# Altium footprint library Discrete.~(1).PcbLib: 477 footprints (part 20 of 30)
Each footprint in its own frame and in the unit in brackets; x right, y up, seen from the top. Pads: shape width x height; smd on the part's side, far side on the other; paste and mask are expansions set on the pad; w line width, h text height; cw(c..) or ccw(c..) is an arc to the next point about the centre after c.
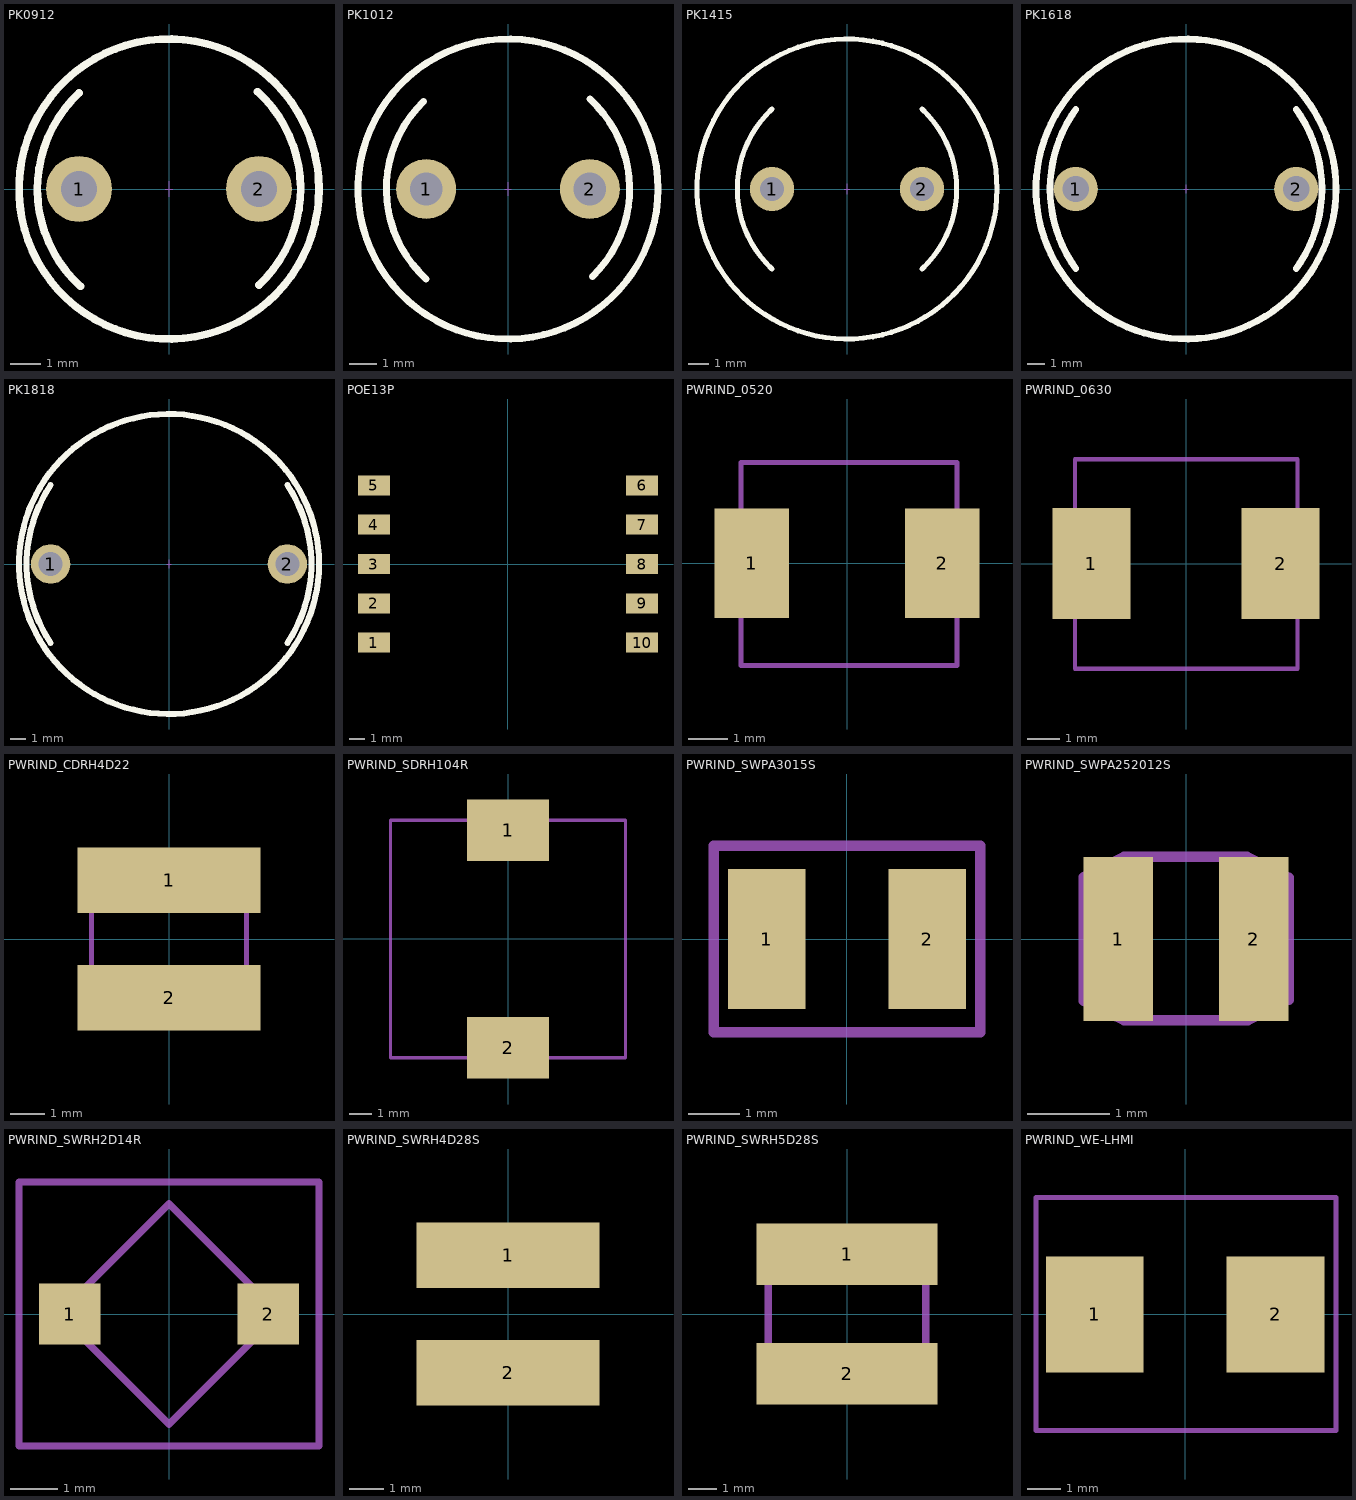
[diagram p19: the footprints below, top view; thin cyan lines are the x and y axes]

## PK0912 [mm] "6*10*14mm(脚距，直径，高）"
pads (2):
  round 2.2 hole 1.2: 1(-3,0) 2(3,0)
Top Overlay:
  circle w0.254: c0,0 r5
  lines w0.254: -3,3.2 ccw(c0,0) -2.951,-3.246 ; 2.951,3.246 cw(c0,0) 3,-3.2
Mechanical 15:
  lines w0.01: -0.127,0 0.127,0 ; 0,-0.254 0,0.254
3D body "PK0912.STEP": height 14.02, standoff -2.78, extent -5,-5 5,5

## PK1012 [mm] "6*11*14mm(脚距，直径，高）"
pads (2):
  round 2.2 hole 1.2: 1(-3,0) 2(3,0)
Top Overlay:
  circle w0.254: c0,0 r5.5
  lines w0.254: -3.101,3.205 ccw(c0,0) -3,-3.3 ; 3,3.3 cw(c0,0) 3.101,-3.205
Mechanical 15:
  lines w0.01: -0.127,0 0.127,0 ; 0,-0.254 0,0.254
3D body "PK1012.STEP": height 14.02, standoff -2.78, extent -5.5,-5.5 5.5,5.5

## PK1415 [mm] "7.5*15*17mm(脚距，直径，高）"
pads (2):
  round 2.2 hole 1.2: 1(-3.75,0) 2(3.75,0)
Top Overlay:
  circle w0.254: c0,0 r7.5
  lines w0.254: -3.75,-4 cw(c0,0) -3.75,4 ; 3.75,-4 ccw(c0,0) 3.75,4
Mechanical 15:
  lines w0.01: -0.127,0 0.127,0 ; 0,-0.254 0,0.254
3D body "PK1415.STEP": height 17.02, standoff -2.78, extent -7.5,-7.5 7.5,7.5

## PK1618 [mm] "12.5*17*20mm(脚距，直径，高）"
pads (2):
  round 2.5 hole 1.5: 1(-6.25,0) 2(6.25,0)
Top Overlay:
  circle w0.381: c0,0 r8.5
  lines w0.381: -6.25,-4.5 cw(c0,0) -6.25,4.5 ; 6.25,-4.5 ccw(c0,0) 6.25,4.5
Mechanical 15:
  lines w0.01: -0.127,0 0.127,0 ; 0,-0.254 0,0.254
3D body "PK1618.STEP": height 20.02, standoff -2.78, extent -8.5,-8.5 8.5,8.5

## PK1818 [mm] "15*19*20mm(脚距，直径，高）"
pads (2):
  round 2.5 hole 1.5: 1(-7.5,0) 2(7.5,0)
Top Overlay:
  circle w0.381: c0,0 r9.5
  lines w0.381: -7.5,-5 cw(c0,0) -7.5,5 ; 7.5,-5 ccw(c0,0) 7.5,5
Mechanical 15:
  lines w0.01: -0.127,0 0.127,0 ; 0,-0.254 0,0.254
3D body "PK1818.STEP": height 20.02, standoff -2.78, extent -9.5,-9.5 9.5,9.5

## POE13P [mm]
pads (10):
  rect 2.03x1.27 smd: 1(-8.51,-5) 2(-8.51,-2.5) 3(-8.51,0) 4(-8.51,2.5) 5(-8.51,5) 6(8.51,5) 7(8.51,2.5) 8(8.51,0) 9(8.51,-2.5) 10(8.51,-5)
3D body "Coilcraft-POE13P-50L.STEP": height 12.7, standoff 0, extent -8.875,-6.73 8.875,6.73

## PWRIND_0520 [mm]
pads (2):
  rect 1.905x2.79 smd: 1(-2.425,0) 2(2.425,0)
Mechanical 13:
  lines w0.127: -2.7,-2.6 -2.7,2.56 2.8,2.56 2.8,-2.6 -2.7,-2.6
3D body "User Library-IHLP2020CZ.STEP": height 3.1, standoff 0.1, extent -2.749,-2.64 2.751,2.56

## PWRIND_0630 [mil]
pads (2):
  rect 95x135 smd: 1(-115,0) 2(115,0)
Mechanical 13:
  lines w5: -134.84,-127.95 -134.84,126.97 135.83,126.97 135.83,-127.95 -134.84,-127.95
3D body "User Library-IHLP-2525CZ.STEP": height 118.11, standoff 0, extent -135.05,-127.36 135.03,127.37

## PWRIND_CDRH4D22 [mm]
pads (2):
  rect 5.3x1.9 smd: 1(0,1.7) 2(0,-1.7)
Mechanical 13:
  lines w0.152: -2.25,-2.25 -2.25,1.55 -1.55,2.25 2.25,2.25 2.25,-2.25 -2.25,-2.25
3D body: height 2.4, standoff 0, extent -2.25,-2.25 2.25,2.25

## PWRIND_SDRH104R [mm]
pads (2):
  rect 3.6x2.7 smd: 1(0,4.775) 2(0,-4.775)
Mechanical 13:
  lines w0.152: -5.15,-5.2 5.15,-5.2 5.15,5.2 -5.15,5.2 -5.15,-5.2
3D body "User Library-IND_MURATA_MBH10145C.STEP": height 6.25, standoff 1.45, extent -5.2,-5.2 5.2,5.2

## PWRIND_SWPA3015S [mm] "Sunloardic SMT Inductor SWPA3015S Series"
height 1.7
pads (2):
  rect 1.5x2.7 smd: 1(-1.55,0) 2(1.55,0)
Mechanical 15:
  lines w0.2: -2.575,-1.8 2.575,-1.8 2.575,1.8 -2.575,1.8 -2.575,-1.8
3D body: height 1.7, standoff 0, extent -1.5,-1.5 1.5,1.5

## PWRIND_SWPA252012S [mm]
pads (2):
  rect 0.85x2 smd: 1(-0.825,0) 2(0.825,0)
Mechanical 13:
  lines w0.127: -1.245,-0.75 -1.245,0.75 -0.75,1 0.737,1 1.25,0.745 1.25,-0.737 0.75,-0.991 -0.75,-0.991 -1.245,-0.75
3D body: height 1.2, standoff 0, extent -1.245,-0.991 1.25,1

## PWRIND_SWRH2D14R [mm]
pads (2):
  rect 1.3x1.3 smd: 1(-2.1,0) 2(2.1,0)
Mechanical 13:
  lines w0.152: -2.333,0 0,2.333 2.333,0 0,-2.333 -2.333,0
Mechanical 15:
  lines w0.152: -3.175,-2.794 -3.175,2.794 3.175,2.794 3.175,-2.794 -3.175,-2.794
3D body: height 1.6, standoff 0, extent -2.333,-2.333 2.333,2.333

## PWRIND_SWRH4D28S [mm]
height 3
pads (2):
  rect 5.3x1.9 smd: 1(0,1.7) 2(0,-1.7)
3D body "User Library-CDRH4D28.STEP": height 2.91, standoff 0, extent -2.475,-2.399 2.425,2.501

## PWRIND_SWRH5D28S [mm]
height 3
pads (2):
  rect 6.3x2.15 smd: 1(0,2.08) 2(0,-2.08)
Mechanical 13:
  lines w0.254: -2.75,-2.75 2.75,-2.75 2.75,2.75 -1.5,2.75 -2.75,1.5 -2.75,-2.75
3D body "User Library-cdrh5d28.STEP": height 3, standoff 0, extent -3.048,-3 2.952,3

## PWRIND_WE-LHMI [mm]
height 3
pads (2):
  rect 2.95x3.5 smd: 1(-2.725,0) 2(2.725,0)
Mechanical 15:
  lines w0.152: -4.496,-3.505 4.547,-3.505 4.547,3.531 -4.496,3.531 -4.496,-3.505
3D body "44816.stp": height 2.7, standoff -0.1, extent -3.65,-3.3 3.65,3.3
